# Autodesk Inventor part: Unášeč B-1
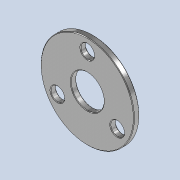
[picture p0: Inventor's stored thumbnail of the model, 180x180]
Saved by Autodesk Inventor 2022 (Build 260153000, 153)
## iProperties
Created: 2025-05
Part Number: Unášeč B-1
Material: Všeobecné
Document SubType Name: Modeling
Designer: jbart
Density: 1 g/cm^3
Appearance: Broušená
Mass: 1464.12 g
Surface Area: 1810.52 cm^2
Volume: 1464.12 cm^3
Author: jbart
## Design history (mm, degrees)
sketch "Náčrt1"
  geometry: L1 (0, 126)-(109.119, -63); L2 (109.119, -63)-(-109.119, -63); L3 (-109.119, -63)-(0, 126); L4 (0, 126)-(0, 0); L5 (0, 0)-(109.119, -63); L6 (0, 0)-(-109.119, -63); C1 r 25 at (0, 126); C2 r 25 at (-109.119, -63); C3 r 25 at (109.119, -63); C4 r 170 at (0, 0); C5 r 60 at (0, 0); 1 further point
  constraints: 12 end point, 6 coincident, 5 centre point, 1 vertical, 7 other
  dimensions: "d0" = 126 distance of L4.end L1.end; "d1" = 50 diameter of C1; "d2" = 50 diameter of C2; "d3" = 50 diameter of C3; "d4" = 340 diameter of C4; "d5" = 120 diameter of C5
extrude "Vysunutí1" new body sketch "Náčrt1" distance "d6" = 20; taper "d7" = 0 deg
chamfer "Zkosení1" distance "d8" = 2; stored, may be unused: second distance "d9" = 2, angle "d10" = 45 deg
node "Těleso1"
